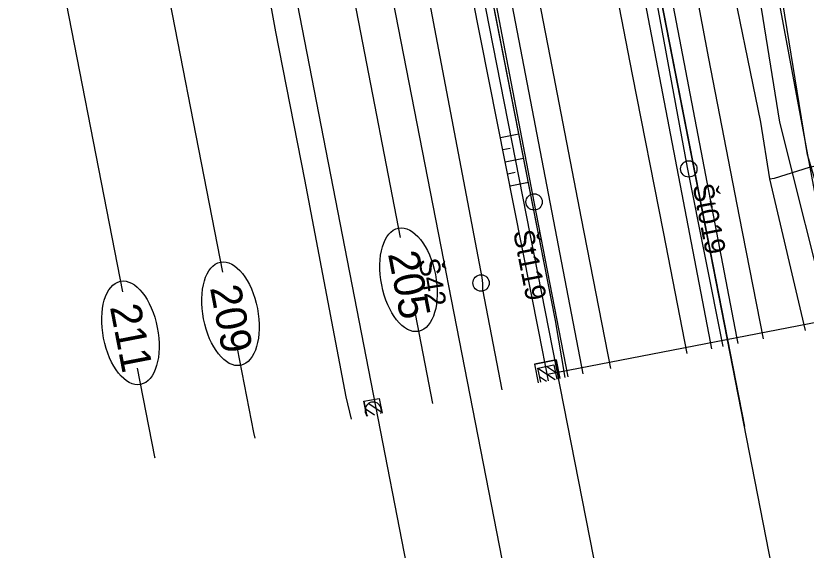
# Model space of a CAD drawing. Extents: x -545967 to -545044, y -1122650 to -1118491.
# Drawn here: x -545744.88 to -545696.59, y -1119257.98 to -1119225.35 of the extents above; entities that cross this region are included whole.
import ezdxf

# ---------------------------------------------------------------- set-up
doc = ezdxf.new("R2010")
doc.units = 0
for name, color, linetype in [('osvětlené plochy-hodnota-obrys', 7, 'Continuous'), ('Vrstva 1', 7, 'Continuous'), ('Vrstva 1 - Koleje', 7, 'Continuous'), ('Vrstva 11', 7, 'Continuous'), ('Vrstva 11 - Trakce', 7, 'Continuous'), ('Vrstva 12 - Trakce zaklady', 7, 'Continuous'), ('Vrstva 2', 7, 'Continuous'), ('Vrstva 26', 7, 'Continuous'), ('Vrstva 26 - silnoproud', 7, 'Continuous'), ('Vrstva 28 - zabzar', 7, 'Continuous'), ('Vrstva 31', 7, 'Continuous'), ('Vrstva 32', 7, 'Continuous'), ('Vrstva 4 - Teren - stezky - prechody - plochy', 7, 'Continuous'), ('Vrstva 43', 7, 'Continuous'), ('Vrstva 44', 7, 'Continuous'), ('Vrstva 48', 7, 'Continuous'), ('Vrstva 49', 7, 'Continuous')]:
    doc.layers.add(name, color=color, linetype=linetype)

msp = doc.modelspace()

# ---------------------------------------------------------------- linework, layer by layer
at = {"layer": 'osvětlené plochy-hodnota-obrys'}
for points in [[(-545700.341, -1119250.428), (-545705.955, -1119221.665), (-545699.039, -1119220.315), (-545660.607, -1119425.918), (-545653.752, -1119372.856), (-545653.095, -1119348.321), (-545657.119, -1119319.988), (-545685.945, -1119192.198), (-545694.33, -1119168.5)], [(-545664.282, -1119515.639), (-545680.447, -1119467.233), (-545736.202, -1119180.74), (-545730.573, -1119179.645)], [(-545730.573, -1119179.645), (-545675.345, -1119462.605), (-545660.82, -1119505.941)], [(-545716.386, -1119223.717), (-545705.994, -1119221.66), (-545669.439, -1119408.759), (-545659.4, -1119462.635), (-545647.69, -1119521.347), (-545640.519, -1119558.729), (-545633.585, -1119589.698), (-545629.517, -1119613.814), (-545623.042, -1119645.057), (-545619.034, -1119667.556), (-545607.519, -1119727.517)], [(-545610.895, -1119760.665), (-545622.836, -1119699.488), (-545637.26, -1119626.872), (-545653.542, -1119543.449), (-545716.386, -1119223.717)]]:
    msp.add_lwpolyline(points, dxfattribs=at)
at = {"layer": 'Vrstva 1'}
for points in [[(-545771.025, -1119042.195), (-545765.518, -1119070.46), (-545759.655, -1119100.537), (-545754.322, -1119127.883), (-545749.142, -1119154.443), (-545741.38, -1119194.232), (-545736.638, -1119218.552), (-545732.259, -1119241.007)], [(-545771.689, -1119071.297), (-545765.82, -1119101.405), (-545760.255, -1119129.935), (-545755.249, -1119155.634), (-545747.474, -1119195.477), (-545742.774, -1119219.556), (-545738.366, -1119242.197)], [(-545732.996, -1119179.254), (-545727.764, -1119206.17), (-545723.954, -1119225.738), (-545721.389, -1119238.891)], [(-545720.48, -1119243.554), (-545719.415, -1119249.019)], [(-545731.349, -1119245.67), (-545730.349, -1119250.8), (-545730.282, -1119251.146)], [(-545737.459, -1119246.86), (-545736.405, -1119252.272), (-545736.391, -1119252.342)]]:
    msp.add_lwpolyline(points, dxfattribs=at)
for centre in [(-545720.886, -1119241.469), (-545731.764, -1119243.545), (-545737.878, -1119244.711)]:
    msp.add_ellipse(centre, major_axis=(0.614, -3.151), ratio=0.521067, dxfattribs=at)
at = {"layer": 'Vrstva 1 - Koleje'}
for points in [[(-545733.999, -1119091.546), (-545732.95, -1119096.936), (-545731.205, -1119105.879), (-545729.373, -1119115.292), (-545728.267, -1119120.965), (-545726.468, -1119130.178), (-545724.605, -1119139.732), (-545722.574, -1119150.154), (-545720.702, -1119159.751), (-545718.638, -1119170.336), (-545716.601, -1119180.775), (-545714.642, -1119190.838), (-545712.795, -1119200.311), (-545711.639, -1119206.25), (-545709.729, -1119216.005), (-545707.216, -1119228.928), (-545705.339, -1119238.544), (-545703.888, -1119245.98)], [(-545738.202, -1119092.228), (-545736.387, -1119101.709), (-545734.567, -1119111.273), (-545732.861, -1119120.206), (-545731.063, -1119129.63), (-545729.36, -1119138.55), (-545727.68, -1119147.349), (-545726.123, -1119155.516), (-545724.233, -1119165.426), (-545722.398, -1119175.037), (-545720.387, -1119185.566), (-545718.546, -1119195.193), (-545717.286, -1119201.759), (-545715.378, -1119211.671), (-545713.882, -1119219.417), (-545712.258, -1119227.812), (-545710.337, -1119237.731), (-545708.555, -1119246.894)], [(-545703.92, -1119220.722), (-545702.554, -1119227.966), (-545700.678, -1119237.615), (-545699.221, -1119245.067)]]:
    msp.add_lwpolyline(points, dxfattribs=at)
at = {"layer": 'Vrstva 11'}
msp.add_lwpolyline([(-545693.484, -1119243.944), (-545696.51, -1119233.839), (-545699.129, -1119217.635), (-545699.471, -1119201.94)], dxfattribs=at)
at = {"layer": 'Vrstva 11 - Trakce'}
for p, q in [((-545695.782, -1119244.029), (-545712.397, -1119247.251)), ((-545712.982, -1119246.858), (-545711.937, -1119247.555)), ((-545712.463, -1119246.754), (-545711.913, -1119247.121)), ((-545712.882, -1119247.375), (-545712.459, -1119247.658)), ((-545723.315, -1119249.023), (-545722.556, -1119249.532)), ((-545723.529, -1119249.331), (-545722.959, -1119249.713))]:
    msp.add_line(p, q, dxfattribs=at)
msp.add_lwpolyline([(-545712.812, -1119247.727), (-545712.985, -1119246.859), (-545712.005, -1119246.663), (-545711.83, -1119247.535)], dxfattribs=at)
msp.add_arc((-545723.045, -1119249.44), 0.5, 336.4487, 225.6988, dxfattribs=at)
at = {"layer": 'Vrstva 12 - Trakce zaklady'}
for p, q in [((-545713.192, -1119246.63), (-545711.873, -1119246.363)), ((-545723.615, -1119248.881), (-545722.686, -1119248.718))]:
    msp.add_line(p, q, dxfattribs=at)
for points in [[(-545711.646, -1119247.499), (-545711.873, -1119246.363), (-545713.192, -1119246.63)], [(-545713.192, -1119246.63), (-545712.975, -1119247.759)], [(-545713.192, -1119246.63), (-545712.975, -1119247.759)], [(-545711.873, -1119246.363), (-545711.646, -1119247.499)], [(-545723.441, -1119249.807), (-545723.615, -1119248.881), (-545722.686, -1119248.718)], [(-545723.615, -1119248.881), (-545723.441, -1119249.807)], [(-545722.686, -1119248.718), (-545722.507, -1119249.624)], [(-545722.686, -1119248.718), (-545722.507, -1119249.624)]]:
    msp.add_lwpolyline(points, dxfattribs=at)
at = {"layer": 'Vrstva 26'}
for points in [[(-545723.4, -1119198.98), (-545720.917, -1119199.104), (-545717.951, -1119198.296), (-545714.968, -1119197.483), (-545713.419, -1119197.11), (-545709.47, -1119196.16), (-545706.908, -1119198.458), (-545704.395, -1119207.525), (-545703.903, -1119209.931), (-545701.434, -1119221.82), (-545699.39, -1119231.84), (-545698.841, -1119235.301), (-545696.65, -1119244.564)], [(-545698.841, -1119235.301), (-545698.529, -1119235.274), (-545696.399, -1119234.598), (-545692.825, -1119233.775), (-545690.864, -1119233.076), (-545688.738, -1119232.03), (-545676.291, -1119229.209), (-545675.638, -1119229.038), (-545670.747, -1119227.759), (-545668.794, -1119227.17), (-545666.647, -1119226.523), (-545664.431, -1119225.855)]]:
    msp.add_lwpolyline(points, dxfattribs=at)
at = {"layer": 'Vrstva 26 - silnoproud'}
for points in [[(-545723.4, -1119198.98), (-545720.917, -1119199.104), (-545717.951, -1119198.296), (-545714.968, -1119197.483), (-545713.419, -1119197.11), (-545711.01, -1119196.68), (-545709.47, -1119196.16), (-545706.908, -1119198.458), (-545704.395, -1119207.525), (-545703.903, -1119209.931), (-545701.434, -1119221.82), (-545699.39, -1119231.84), (-545698.841, -1119235.301), (-545696.65, -1119244.564)], [(-545723.4, -1119198.98), (-545720.917, -1119199.104), (-545717.951, -1119198.296), (-545714.968, -1119197.483), (-545713.419, -1119197.11), (-545711.01, -1119196.68), (-545709.47, -1119196.16), (-545706.908, -1119198.458), (-545704.395, -1119207.525), (-545703.903, -1119209.931), (-545701.434, -1119221.82), (-545699.39, -1119231.84), (-545698.841, -1119235.301), (-545696.65, -1119244.564)], [(-545708.67, -1119197.64), (-545708.32, -1119197.58), (-545708.6, -1119196.51), (-545704.54, -1119197.6), (-545702.23, -1119206.95), (-545699.9, -1119221.45), (-545698.219, -1119231.843), (-545695.098, -1119244.26)], [(-545698.841, -1119235.301), (-545698.529, -1119235.274), (-545696.399, -1119234.598), (-545692.825, -1119233.775), (-545690.864, -1119233.076), (-545688.738, -1119232.03), (-545676.291, -1119229.209), (-545675.638, -1119229.038), (-545670.747, -1119227.759), (-545668.794, -1119227.17), (-545666.647, -1119226.523), (-545664.431, -1119225.855)]]:
    msp.add_lwpolyline(points, dxfattribs=at)
at = {"layer": 'Vrstva 28 - zabzar'}
msp.add_lwpolyline([(-545724.371, -1119249.989), (-545724.69, -1119248.61), (-545727.23, -1119235.34), (-545728.99, -1119226.34), (-545732.03, -1119209.67), (-545734.16, -1119200.74), (-545735.82, -1119191.07), (-545737.79, -1119181.49), (-545737.14, -1119173.49), (-545736.89, -1119172.51), (-545735.08, -1119167.68), (-545734.54, -1119163.85), (-545734.59, -1119161.66), (-545735.09, -1119157.79), (-545736.08, -1119151.98), (-545737.73, -1119145.12), (-545739.97, -1119133.32), (-545740.77, -1119128.56), (-545744.45, -1119110.05), (-545745.46, -1119105.77), (-545746.9, -1119097.66), (-545750.31, -1119079.79)], dxfattribs=at)
at = {"layer": 'Vrstva 31'}
msp.add_lwpolyline([(-545724.371, -1119249.989), (-545724.69, -1119248.61), (-545727.23, -1119235.34), (-545728.99, -1119226.34), (-545732.03, -1119209.67), (-545734.16, -1119200.74), (-545735.82, -1119191.07), (-545737.79, -1119181.49), (-545737.14, -1119173.49), (-545736.89, -1119172.51), (-545735.08, -1119167.68), (-545734.54, -1119163.85), (-545734.59, -1119161.66), (-545735.09, -1119157.79), (-545736.08, -1119151.98), (-545737.73, -1119145.12), (-545739.97, -1119133.32), (-545740.77, -1119128.56), (-545744.45, -1119110.05), (-545745.46, -1119105.77), (-545746.9, -1119097.66), (-545750.31, -1119079.79)], dxfattribs=at)
at = {"layer": 'Vrstva 32'}
msp.add_lwpolyline([(-545724.371, -1119249.989), (-545724.69, -1119248.61), (-545727.23, -1119235.34), (-545728.99, -1119226.34), (-545732.03, -1119209.67), (-545734.16, -1119200.74), (-545735.66, -1119191.53), (-545735.82, -1119191.07), (-545737.79, -1119181.49), (-545737.14, -1119173.49), (-545736.89, -1119172.51), (-545735.08, -1119167.68), (-545734.54, -1119163.85), (-545734.59, -1119161.66), (-545735.09, -1119157.79), (-545736.08, -1119151.98), (-545737.73, -1119145.12), (-545739.97, -1119133.32), (-545740.77, -1119128.56), (-545744.45, -1119110.05), (-545745.46, -1119105.77), (-545746.9, -1119097.66), (-545750.31, -1119079.79)], dxfattribs=at)
at = {"layer": 'Vrstva 4 - Teren - stezky - prechody - plochy'}
for points in [[(-545711.324, -1119247.435), (-545711.901, -1119243.963), (-545720.224, -1119201.665), (-545721.285, -1119195.757), (-545731.546, -1119141.712), (-545737.081, -1119112.42), (-545743.441, -1119079.103), (-545754.278, -1119022.005), (-545764.127, -1118971.243), (-545774.702, -1118917.119), (-545786.098, -1118858.181), (-545797.005, -1118803.413), (-545807.661, -1118749.422), (-545819.911, -1118686.431), (-545828.531, -1118641.36), (-545850.15, -1118530.525), (-545851.156, -1118525.517)], [(-545710.225, -1119247.22), (-545719.004, -1119201.386), (-545730.622, -1119141.385), (-545736.208, -1119112.206), (-545742.564, -1119078.927), (-545753.414, -1119021.814), (-545763.359, -1118970.942), (-545773.922, -1118916.709), (-545785.328, -1118858.188), (-545796.206, -1118802.914), (-545806.845, -1118748.63), (-545819.206, -1118686.191), (-545827.818, -1118641.013), (-545849.345, -1118530.249), (-545850.409, -1118525.371)], [(-545706.355, -1119218.803), (-545707.51, -1119218.932), (-545702.452, -1119245.262), (-545702.369, -1119245.683)], [(-545706.355, -1119218.803), (-545705.856, -1119218.828), (-545700.854, -1119244.947), (-545700.771, -1119245.37)]]:
    msp.add_lwpolyline(points, dxfattribs=at)
at = {"layer": 'Vrstva 43'}
for centre in [(-545703.764, -1119234.702), (-545713.214, -1119236.715), (-545716.454, -1119241.667)]:
    msp.add_circle(centre, 0.5, dxfattribs=at)
at = {"layer": 'Vrstva 44'}
for points in [[(-545744.065, -1119094.166), (-545734.822, -1119146.139), (-545734.752, -1119146.549), (-545734.659, -1119146.89), (-545724.724, -1119197.313), (-545724.661, -1119197.687), (-545724.663, -1119198.006), (-545716.416, -1119241.322), (-545716.376, -1119241.688), (-545716.362, -1119242.059), (-545715.179, -1119248.19)], [(-545701.67, -1119245.546), (-545703.847, -1119234.609), (-545711.114, -1119195.247)], [(-545711.13, -1119247.397), (-545713.208, -1119236.715), (-545720.909, -1119196.537), (-545721.01, -1119196.412)]]:
    msp.add_lwpolyline(points, dxfattribs=at)
at = {"layer": 'Vrstva 48'}
for p, q in [((-545715.266, -1119232.789), (-545714.143, -1119232.567)), ((-545715.12, -1119233.525), (-545714.672, -1119233.436)), ((-545714.974, -1119234.261), (-545713.854, -1119234.038)), ((-545714.829, -1119234.996), (-545714.381, -1119234.908)), ((-545714.683, -1119235.732), (-545713.564, -1119235.51))]:
    msp.add_line(p, q, dxfattribs=at)
at = {"layer": 'Vrstva 49'}
for points in [[(-545712.345, -1119247.635), (-545712.918, -1119244.626), (-545721.552, -1119201.108), (-545732.642, -1119141.942), (-545733.194, -1119140.665), (-545738.437, -1119113.17), (-545744.258, -1119082.787), (-545744.781, -1119080.348), (-545754.155, -1119031.651), (-545755.213, -1119026.18), (-545765.268, -1118974.147), (-545765.5, -1118972.759), (-545775.821, -1118920.177), (-545776.085, -1118918.771), (-545787.25, -1118861.285), (-545787.565, -1118859.78), (-545796.822, -1118811.001)], [(-545711.324, -1119247.435), (-545711.901, -1119243.963), (-545720.224, -1119201.665), (-545721.285, -1119195.757), (-545721.943, -1119195.521), (-545732.082, -1119141.82), (-545732.265, -1119140.515), (-545737.739, -1119112.717), (-545743.315, -1119083.132), (-545744.039, -1119079.561), (-545753.263, -1119031.334), (-545754.002, -1119028.935), (-545754.148, -1119025.929), (-545754.487, -1119024.319), (-545754.825, -1119024.298), (-545764.544, -1118973.992), (-545764.787, -1118972.577), (-545775.108, -1118920.03), (-545775.396, -1118918.541), (-545786.585, -1118861.093), (-545786.924, -1118859.548), (-545796.323, -1118810.897)]]:
    msp.add_lwpolyline(points, dxfattribs=at)

# ---------------------------------------------------------------- texts
at = {"layer": 'Vrstva 2'}
for s, p in [('205', (-545722.147, -1119239.884)), ('209', (-545733.024, -1119241.96)), ('211', (-545739.138, -1119243.127))]:
    msp.add_text(s, height=1.875, rotation=280.9117, dxfattribs=at).set_placement(p)
at = {"layer": 'Vrstva 43'}
for s, rotation, p in [('Št019', 280.9998, (-545703.538, -1119235.714)), ('Št119', 280.9998, (-545714.502, -1119238.538)), ('Š42', 279.317, (-545720.275, -1119240.253))]:
    msp.add_text(s, height=1.25, rotation=rotation, dxfattribs=at).set_placement(p)

doc.saveas('drawing.dxf')
